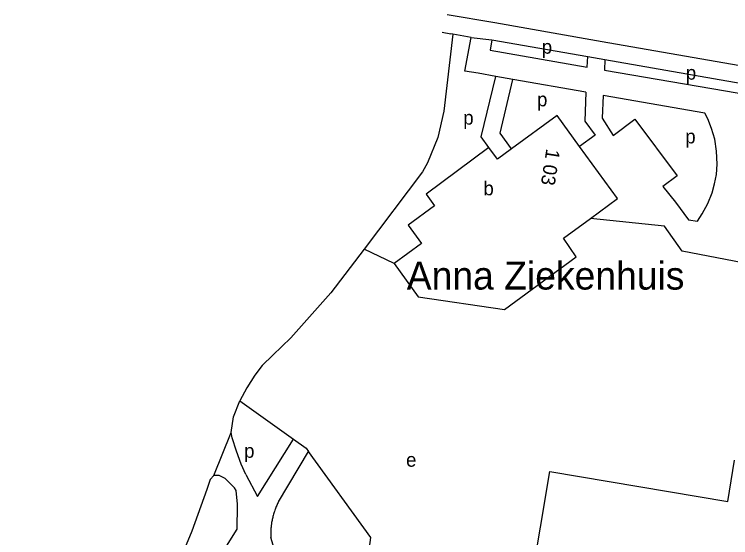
# Model space of a CAD drawing. Extents: x 161093 to 163177, y 379000 to 380904.
# Drawn here: x 161137.9 to 161343.5, y 380753.5 to 380903.5 of the extents above; entities that cross this region are included whole.
import ezdxf

# ---------------------------------------------------------------- set-up
doc = ezdxf.new("R2010")
doc.units = 0
for name, color, linetype in [('BLT_Basislijn', 7, 'Continuous'), ('BLT_Bebouwing', 7, 'Continuous'), ('BLT_Bebouwing_beschrifting', 7, 'Continuous'), ('BLT_Centroide', 7, 'Continuous'), ('BLT_Huisnummer', 7, 'Continuous'), ('BLT_Vlakafsluiter', 7, 'Continuous')]:
    doc.layers.add(name, color=color, linetype=linetype)

msp = doc.modelspace()

# ---------------------------------------------------------------- linework, layer by layer
at = {"layer": 'BLT_Basislijn'}
for p, q in [((161262.13, 380903.54), (161275.81, 380901.16)), ((161275.81, 380901.16), (161303.28, 380896.37)), ((161260.7, 380898.4), (161263.11, 380897.98)), ((161263.71, 380897.87), (161261.15, 380875.81)), ((161263.71, 380897.87), (161263.11, 380897.98)), ((161268.94, 380896.91), (161263.71, 380897.87)), ((161268.94, 380896.91), (161274.95, 380896.23)), ((161303.28, 380896.37), (161308.24, 380895.51)), ((161308.24, 380895.51), (161354.49, 380887.45)), ((161302.42, 380891.45), (161307.39, 380890.58)), ((161307.39, 380890.58), (161353.63, 380882.52)), ((161301.9, 380881.19), (161301.58, 380872.94)), ((161306.87, 380880.31), (161306.62, 380873.79)), ((161336.09, 380875.18), (161306.87, 380880.31)), ((161301.58, 380872.94), (161304.56, 380868.86)), ((161304.56, 380868.86), (161300.11, 380865.63)), ((161246.84, 380832.12), (161238.24, 380836.23)), ((161200.8, 380788.09), (161202.54, 380792.73)), ((161202.54, 380792.73), (161217.97, 380781.74)), ((161200.09, 380783.66), (161200.8, 380788.09)), ((161240.23, 380753.55), (161222.3, 380778.18)), ((161204.33, 380771.55), (161207.67, 380765.27)), ((161239.37, 380747.93), (161240.23, 380753.55))]:
    msp.add_line(p, q, dxfattribs=at)
for points in [[(161270.95, 380886.63), (161267.17, 380887.29), (161268.94, 380896.91)], [(161274.95, 380896.23), (161274.43, 380893.28), (161302.26, 380888.43), (161302.42, 380891.45)], [(161274.95, 380896.23), (161302.42, 380891.45)], [(161307.39, 380890.58), (161307.22, 380887.56), (161353.2, 380879.67), (161353.63, 380882.52)], [(161276.05, 380885.73), (161270.95, 380886.63)], [(161274.07, 380865.36), (161271.85, 380868.39), (161276.05, 380885.73)], [(161280.98, 380884.86), (161276.05, 380885.73)], [(161280.56, 380864.96), (161277.26, 380869.47), (161280.98, 380884.86)], [(161301.9, 380881.19), (161280.98, 380884.86)], [(161261.15, 380875.81), (161259.37, 380868.26), (161256.49, 380860.95), (161255.04, 380858.35), (161238.24, 380836.23)], [(161333.95, 380844.23), (161335.28, 380846.33), (161336.94, 380849.3), (161338.12, 380852.33), (161338.83, 380854.91), (161339.36, 380857.65), (161339.55, 380860.59), (161339.39, 380864.3), (161338.87, 380867.76), (161337.99, 380870.8), (161336.88, 380873.6), (161336.09, 380875.18)], [(161306.62, 380873.79), (161309.73, 380868.77), (161315.98, 380873.46), (161328.09, 380857.19), (161323.99, 380854.19), (161327.67, 380849.68)], [(161327.67, 380849.68), (161331.4, 380844.63), (161333.95, 380844.23)], [(161346.14, 380785.95), (161349.58, 380808.42), (161372.17, 380804.95), (161372.86, 380809.68), (161373.72, 380811.46), (161374.38, 380813.15), (161374.79, 380814.92), (161374.93, 380817.1), (161374.71, 380819.39), (161374.12, 380821.46), (161373.5, 380822.94), (161372.72, 380824.28), (161372.01, 380825.23), (161370.74, 380826.58), (161369.24, 380827.77), (161367.27, 380828.87), (161365.36, 380829.6), (161363.33, 380829.99), (161361.36, 380830.11), (161359.42, 380829.89), (161329.53, 380835.64), (161324.48, 380842.84), (161303.23, 380845.01)], [(161238.24, 380836.23), (161228.67, 380823.65), (161217.22, 380810.77), (161212.09, 380805.8), (161209.04, 380802.83), (161206.93, 380800.05), (161204.57, 380796.45), (161202.54, 380792.73)], [(161204.33, 380771.55), (161202.99, 380774.6), (161201.6, 380778.26), (161200.42, 380782.11), (161200.09, 380783.66)], [(161207.67, 380765.27), (161217.97, 380781.74)], [(161217.97, 380781.74), (161221.59, 380779.16), (161222.3, 380778.18)], [(161213.68, 380763.8), (161222.3, 380778.18)], [(161195.11, 380771.29), (161194.08, 380770.13)], [(161196.17, 380771.29), (161195.11, 380771.29)], [(161200.1, 380768.68), (161198.33, 380770.42), (161196.64, 380771.29), (161196.17, 380771.29)], [(161194.08, 380770.13), (161193.07, 380767.27), (161188.85, 380755.34), (161182.64, 380740.65), (161180.86, 380736.75), (161177.87, 380731.61), (161174.09, 380726.3), (161170.6, 380723.76)], [(161201.89, 380762.72), (161201.9, 380763.04), (161201.54, 380767.03), (161201.05, 380767.73), (161200.1, 380768.68)], [(161201.79, 380755.87), (161201.89, 380762.72)], [(161213.68, 380763.8), (161213.54, 380763.53), (161213.41, 380763.26), (161213.29, 380762.99), (161213.17, 380762.72), (161213.05, 380762.44), (161212.93, 380762.16), (161212.82, 380761.88), (161212.72, 380761.6), (161212.61, 380761.32), (161212.52, 380761.03), (161212.42, 380760.75), (161212.33, 380760.46), (161212.25, 380760.17), (161212.17, 380759.88), (161212.09, 380759.59), (161212.02, 380759.3), (161211.95, 380759), (161211.88, 380758.71), (161211.82, 380758.42), (161211.77, 380758.12), (161211.72, 380757.83), (161211.67, 380757.53), (161211.63, 380757.23)], [(161138.79, 380620.29), (161137.86, 380627.5), (161138.15, 380632.61), (161140.46, 380645.87), (161144.66, 380655.77), (161157.92, 380674.97), (161171.21, 380695.15), (161177.54, 380707.34), (161182.78, 380720.38), (161193.14, 380742.04), (161201.79, 380755.87)], [(161211.63, 380757.23), (161211.61, 380757.07), (161211.59, 380756.91), (161211.57, 380756.75), (161211.55, 380756.58), (161211.53, 380756.42), (161211.52, 380756.26), (161211.51, 380756.1), (161211.49, 380755.93), (161211.48, 380755.77), (161211.47, 380755.61), (161211.47, 380755.44), (161211.46, 380755.28), (161211.45, 380755.12), (161211.45, 380754.95), (161211.45, 380754.79), (161211.44, 380754.62), (161211.44, 380754.46), (161211.44, 380754.3), (161211.45, 380754.13), (161211.45, 380753.97), (161211.45, 380753.81), (161211.46, 380753.64), (161211.47, 380753.48)], [(161216.25, 380743.62), (161213.02, 380748.47), (161211.47, 380753.48)]]:
    msp.add_lwpolyline(points, dxfattribs=at)
at = {"layer": 'BLT_Bebouwing'}
for p, q in [((161274.07, 380865.36), (161256.04, 380851.93)), ((161295.44, 380839.32), (161303.23, 380845.01)), ((161254.7, 380837.86), (161246.84, 380832.12)), ((161246.84, 380832.12), (161253.81, 380822.58))]:
    msp.add_line(p, q, dxfattribs=at)
for points in [[(161300.11, 380865.63), (161293.63, 380874.5), (161280.56, 380864.96)], [(161280.56, 380864.96), (161276.52, 380862), (161274.07, 380865.36)], [(161303.23, 380845.01), (161311.02, 380850.69), (161300.11, 380865.63)], [(161256.04, 380851.93), (161258.47, 380848.6), (161250.89, 380843.07), (161254.7, 380837.86)], [(161253.81, 380822.58), (161278.54, 380818.87), (161299.07, 380834.02), (161295.44, 380839.32)], [(161262.04, 380576.82), (161266.7, 380607.19), (161238.48, 380612.29), (161248.7, 380668.91), (161251.34, 380668.43), (161254.72, 380687.17), (161261.86, 380685.88), (161264.78, 380702.03), (161258.81, 380702.96), (161265.16, 380743.79), (161286.19, 380740.52), (161291.52, 380772.43), (161342.69, 380763.87), (161344.54, 380775.72)]]:
    msp.add_lwpolyline(points, dxfattribs=at)
at = {"layer": 'BLT_Vlakafsluiter'}
msp.add_line((161195.11, 380771.29), (161200.09, 380783.66), dxfattribs=at)

# ---------------------------------------------------------------- texts
at = {"layer": 'BLT_Bebouwing_beschrifting'}
msp.add_text('Anna Ziekenhuis', height=8, dxfattribs=at).set_placement((161250.49, 380824.62))
at = {"layer": 'BLT_Centroide'}
for s, p in [('p', (161289.23, 380892.25)), ('p', (161330.59, 380884.8)), ('p', (161287.88, 380877.16)), ('p', (161266.71, 380871.91)), ('p', (161330.43, 380866.54)), ('b', (161272.49, 380851.65)), ('p', (161203.81, 380776.38)), ('e', (161250.3, 380773.82))]:
    msp.add_text(s, height=4, dxfattribs=at).set_placement(p)
at = {"layer": 'BLT_Huisnummer'}
msp.add_text('1 03', height=4, rotation=261.1283, dxfattribs=at).set_placement((161290.57, 380865.13))

doc.saveas('drawing.dxf')
